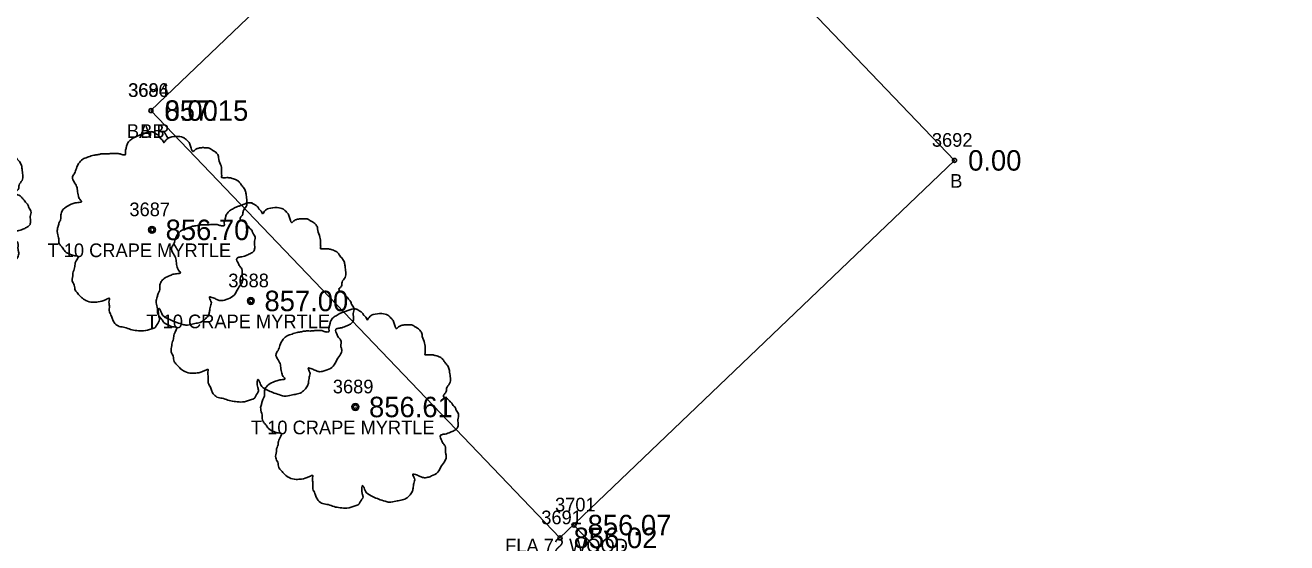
# Model space of a CAD drawing. Extents: x 1622501 to 1626664, y 1117816 to 1121579.
# Drawn here: x 1624818.4 to 1624910.8, y 1120179.9 to 1120217.8 of the extents above; entities that cross this region are included whole.
import ezdxf

# ---------------------------------------------------------------- set-up
doc = ezdxf.new("R2010")
doc.units = 0
for name, color, linetype in [('RD_EX_Bldg', 7, 'Continuous'), ('RD_EX_Bldg_txCode', 7, 'Continuous'), ('RD_EX_Fence_Other', 7, 'Continuous'), ('RD_EX_Fence_Other_txCode', 7, 'Continuous'), ('RD_EX_TX_Bldg_ELEV', 7, 'Continuous'), ('RD_EX_TX_Fence_Other_ELEV', 7, 'Continuous'), ('RD_EX_TX_VEG_ELEV', 7, 'Continuous'), ('RD_EX_VEG', 7, 'Continuous'), ('RD_EX_VEG_txCode', 7, 'Continuous'), ('RD_SMD_Locator', 7, 'Continuous')]:
    doc.layers.add(name, color=color, linetype=linetype)

msp = doc.modelspace()

# ---------------------------------------------------------------- linework, layer by layer
at = {"layer": 'RD_EX_Bldg'}
msp.add_lwpolyline([(1624827.624, 1120211.526), (1624857.59, 1120180.217), (1624886.487, 1120207.875), (1624856.521, 1120239.184), (1624827.624, 1120211.526)], dxfattribs=at)
at = {"layer": 'RD_EX_Fence_Other'}
msp.add_lwpolyline([(1624858.614, 1120181.158), (1624885.841, 1120152.998), (1624885.793, 1120151.157), (1624925.786, 1120193.73), (1624921.287, 1120199.2), (1624921.287, 1120199.2), (1624965.414, 1120242.441), (1624960.474, 1120248.561)], dxfattribs=at)
at = {"layer": 'RD_EX_VEG'}
for centre, radius in [((1624827.703, 1120202.787), 0.25), ((1624827.691, 1120202.768), 0.0001), ((1624834.945, 1120197.577), 0.25), ((1624834.933, 1120197.558), 0.0001), ((1624842.605, 1120189.807), 0.25), ((1624842.592, 1120189.788), 0.0001)]:
    msp.add_circle(centre, radius, dxfattribs=at)
for points in [[(1624815.641, 1120199.363), (1624815.566, 1120199.538), (1624815.516, 1120199.788), (1624815.591, 1120199.763), (1624815.766, 1120199.713), (1624816.041, 1120199.588), (1624816.266, 1120199.513), (1624816.591, 1120199.538), (1624816.865, 1120199.638), (1624817.315, 1120199.913), (1624817.59, 1120200.388), (1624817.865, 1120200.787), (1624817.94, 1120201.112), (1624817.89, 1120201.337), (1624817.865, 1120201.837), (1624817.665, 1120202.087), (1624817.615, 1120202.212), (1624817.515, 1120202.612), (1624817.59, 1120202.662), (1624817.865, 1120202.712), (1624818.24, 1120202.836), (1624818.515, 1120202.961), (1624818.74, 1120203.136), (1624818.815, 1120203.361), (1624818.79, 1120203.761), (1624818.84, 1120204.161), (1624818.765, 1120204.311), (1624818.665, 1120204.461), (1624818.59, 1120204.661), (1624818.44, 1120204.811), (1624818.34, 1120204.961), (1624818.24, 1120205.06), (1624818.115, 1120205.21), (1624817.94, 1120205.335), (1624817.79, 1120205.385), (1624817.74, 1120205.535), (1624817.89, 1120205.735), (1624817.94, 1120205.835), (1624817.965, 1120206.06), (1624818.19, 1120206.41), (1624818.24, 1120206.81), (1624818.19, 1120207.235), (1624818.14, 1120207.509), (1624817.99, 1120207.784), (1624817.79, 1120208.034), (1624817.665, 1120208.209), (1624817.49, 1120208.334), (1624817.165, 1120208.459), (1624816.915, 1120208.509), (1624816.566, 1120208.509), (1624816.366, 1120208.559), (1624816.391, 1120208.609), (1624816.391, 1120208.759), (1624816.391, 1120209.034), (1624816.316, 1120209.484), (1624816.166, 1120209.983), (1624816.166, 1120210.008), (1624816.066, 1120210.258), (1624815.841, 1120210.458), (1624815.666, 1120210.558), (1624815.466, 1120210.683), (1624815.216, 1120210.708), (1624814.916, 1120210.708), (1624814.641, 1120210.658), (1624814.441, 1120210.558), (1624814.267, 1120210.433), (1624814.192, 1120210.583), (1624814.092, 1120210.883), (1624814.042, 1120211.033), (1624813.892, 1120211.208), (1624813.667, 1120211.408), (1624813.217, 1120211.533), (1624812.592, 1120211.458), (1624812.292, 1120211.258), (1624812.142, 1120211.083), (1624812.093, 1120211.208), (1624811.893, 1120211.408), (1624811.793, 1120211.583), (1624811.618, 1120211.708), (1624811.468, 1120211.808), (1624811.368, 1120211.858)], [(1624827.835, 1120209.954), (1624827.535, 1120209.979), (1624827.211, 1120209.879), (1624826.961, 1120209.779), (1624826.736, 1120209.704), (1624826.511, 1120209.604), (1624826.211, 1120209.43), (1624825.986, 1120209.23), (1624825.861, 1120208.98), (1624825.811, 1120208.755), (1624825.761, 1120208.48), (1624825.761, 1120208.305), (1624825.636, 1120208.28), (1624825.486, 1120208.305), (1624825.236, 1120208.38), (1624824.987, 1120208.38), (1624824.737, 1120208.38), (1624824.387, 1120208.355), (1624824.037, 1120208.355), (1624823.762, 1120208.305), (1624823.437, 1120208.255), (1624823.062, 1120208.13), (1624822.713, 1120208.005), (1624822.413, 1120207.755), (1624822.163, 1120207.28), (1624822.038, 1120206.931), (1624821.888, 1120206.681), (1624822.038, 1120206.231), (1624822.213, 1120205.881), (1624822.238, 1120205.681), (1624822.313, 1120205.256), (1624822.413, 1120205.031), (1624822.538, 1120204.831), (1624822.463, 1120204.807), (1624822.088, 1120204.757), (1624821.788, 1120204.657), (1624821.363, 1120204.432), (1624821.138, 1120204.207), (1624821.038, 1120203.882), (1624821.013, 1120203.532), (1624820.913, 1120203.332), (1624820.838, 1120203.057), (1624820.813, 1120202.982), (1624820.763, 1120202.657), (1624820.863, 1120202.208), (1624820.888, 1120201.858), (1624821.013, 1120201.633), (1624821.163, 1120201.458), (1624821.338, 1120201.208), (1624821.738, 1120200.983), (1624822.063, 1120200.883), (1624822.263, 1120200.858), (1624822.088, 1120200.358), (1624822.038, 1120200.009), (1624821.913, 1120199.609), (1624821.913, 1120199.534), (1624821.863, 1120199.059), (1624822.013, 1120198.734), (1624822.088, 1120198.359), (1624822.263, 1120198.134), (1624822.538, 1120197.835), (1624822.862, 1120197.61), (1624823.362, 1120197.485), (1624823.762, 1120197.51), (1624824.337, 1120197.685), (1624824.587, 1120197.76), (1624824.562, 1120197.585), (1624824.587, 1120197.21), (1624824.587, 1120196.785), (1624824.737, 1120196.46), (1624824.837, 1120196.185), (1624824.987, 1120195.935), (1624825.311, 1120195.711), (1624825.711, 1120195.636), (1624826.136, 1120195.486), (1624826.586, 1120195.411), (1624827.086, 1120195.386), (1624827.685, 1120195.536), (1624827.96, 1120195.661), (1624828.06, 1120195.835), (1624828.26, 1120196.21), (1624828.21, 1120196.435), (1624828.235, 1120197.035), (1624828.335, 1120196.86), (1624828.51, 1120196.51), (1624829.01, 1120196.21), (1624829.41, 1120196.035), (1624829.884, 1120195.885), (1624830.184, 1120195.81), (1624830.659, 1120195.885), (1624831.034, 1120195.96), (1624831.409, 1120196.085), (1624831.709, 1120196.36), (1624831.884, 1120196.635), (1624831.934, 1120196.91), (1624832.008, 1120197.285), (1624832.058, 1120197.46)], [(1624832.058, 1120197.46), (1624831.984, 1120197.635), (1624831.934, 1120197.885), (1624832.008, 1120197.86), (1624832.183, 1120197.81), (1624832.458, 1120197.685), (1624832.683, 1120197.61), (1624833.008, 1120197.635), (1624833.283, 1120197.735), (1624833.733, 1120198.01), (1624834.008, 1120198.484), (1624834.282, 1120198.884), (1624834.357, 1120199.209), (1624834.307, 1120199.434), (1624834.282, 1120199.934), (1624834.083, 1120200.184), (1624834.033, 1120200.308), (1624833.933, 1120200.708), (1624834.008, 1120200.758), (1624834.282, 1120200.808), (1624834.657, 1120200.933), (1624834.932, 1120201.058), (1624835.157, 1120201.233), (1624835.232, 1120201.458), (1624835.207, 1120201.858), (1624835.257, 1120202.258), (1624835.182, 1120202.408), (1624835.082, 1120202.557), (1624835.007, 1120202.757), (1624834.857, 1120202.907), (1624834.757, 1120203.057), (1624834.657, 1120203.157), (1624834.532, 1120203.307), (1624834.357, 1120203.432), (1624834.208, 1120203.482), (1624834.158, 1120203.632), (1624834.307, 1120203.832), (1624834.357, 1120203.932), (1624834.382, 1120204.157), (1624834.607, 1120204.507), (1624834.657, 1120204.906), (1624834.607, 1120205.331), (1624834.557, 1120205.606), (1624834.407, 1120205.881), (1624834.208, 1120206.131), (1624834.083, 1120206.306), (1624833.908, 1120206.431), (1624833.583, 1120206.556), (1624833.333, 1120206.606), (1624832.983, 1120206.606), (1624832.783, 1120206.656), (1624832.808, 1120206.706), (1624832.808, 1120206.856), (1624832.808, 1120207.131), (1624832.733, 1120207.58), (1624832.583, 1120208.08), (1624832.583, 1120208.105), (1624832.483, 1120208.355), (1624832.258, 1120208.555), (1624832.083, 1120208.655), (1624831.884, 1120208.78), (1624831.634, 1120208.805), (1624831.334, 1120208.805), (1624831.059, 1120208.755), (1624830.859, 1120208.655), (1624830.684, 1120208.53), (1624830.609, 1120208.68), (1624830.509, 1120208.98), (1624830.459, 1120209.13), (1624830.309, 1120209.305), (1624830.084, 1120209.504), (1624829.634, 1120209.629), (1624829.01, 1120209.554), (1624828.71, 1120209.355), (1624828.56, 1120209.18), (1624828.51, 1120209.305), (1624828.31, 1120209.504), (1624828.21, 1120209.679), (1624828.035, 1120209.804), (1624827.885, 1120209.904), (1624827.785, 1120209.954)], [(1624835.077, 1120204.744), (1624834.777, 1120204.769), (1624834.453, 1120204.669), (1624834.203, 1120204.569), (1624833.978, 1120204.494), (1624833.753, 1120204.394), (1624833.453, 1120204.219), (1624833.228, 1120204.019), (1624833.103, 1120203.77), (1624833.053, 1120203.545), (1624833.003, 1120203.27), (1624833.003, 1120203.095), (1624832.878, 1120203.07), (1624832.728, 1120203.095), (1624832.478, 1120203.17), (1624832.229, 1120203.17), (1624831.979, 1120203.17), (1624831.629, 1120203.145), (1624831.279, 1120203.145), (1624831.004, 1120203.095), (1624830.679, 1120203.045), (1624830.304, 1120202.92), (1624829.955, 1120202.795), (1624829.655, 1120202.545), (1624829.405, 1120202.07), (1624829.28, 1120201.72), (1624829.13, 1120201.471), (1624829.28, 1120201.021), (1624829.455, 1120200.671), (1624829.48, 1120200.471), (1624829.555, 1120200.046), (1624829.655, 1120199.821), (1624829.78, 1120199.621), (1624829.705, 1120199.596), (1624829.33, 1120199.546), (1624829.03, 1120199.446), (1624828.605, 1120199.222), (1624828.38, 1120198.997), (1624828.28, 1120198.672), (1624828.255, 1120198.322), (1624828.155, 1120198.122), (1624828.08, 1120197.847), (1624828.055, 1120197.772), (1624828.005, 1120197.447), (1624828.105, 1120196.997), (1624828.13, 1120196.648), (1624828.255, 1120196.423), (1624828.405, 1120196.248), (1624828.58, 1120195.998), (1624828.98, 1120195.773), (1624829.305, 1120195.673), (1624829.505, 1120195.648), (1624829.33, 1120195.148), (1624829.28, 1120194.798), (1624829.155, 1120194.399), (1624829.155, 1120194.324), (1624829.105, 1120193.849), (1624829.255, 1120193.524), (1624829.33, 1120193.149), (1624829.505, 1120192.924), (1624829.78, 1120192.624), (1624830.104, 1120192.4), (1624830.604, 1120192.275), (1624831.004, 1120192.3), (1624831.579, 1120192.474), (1624831.829, 1120192.549), (1624831.804, 1120192.375), (1624831.829, 1120192), (1624831.829, 1120191.575), (1624831.979, 1120191.25), (1624832.079, 1120190.975), (1624832.229, 1120190.725), (1624832.553, 1120190.5), (1624832.953, 1120190.425), (1624833.378, 1120190.275), (1624833.828, 1120190.2), (1624834.328, 1120190.175), (1624834.927, 1120190.325), (1624835.202, 1120190.45), (1624835.302, 1120190.625), (1624835.502, 1120191), (1624835.452, 1120191.225), (1624835.477, 1120191.825), (1624835.577, 1120191.65), (1624835.752, 1120191.3), (1624836.252, 1120191), (1624836.652, 1120190.825), (1624837.126, 1120190.675), (1624837.426, 1120190.6), (1624837.901, 1120190.675), (1624838.276, 1120190.75), (1624838.651, 1120190.875), (1624838.951, 1120191.15), (1624839.126, 1120191.425), (1624839.176, 1120191.7), (1624839.25, 1120192.075), (1624839.3, 1120192.25)], [(1624839.3, 1120192.25), (1624839.226, 1120192.425), (1624839.176, 1120192.674), (1624839.25, 1120192.649), (1624839.425, 1120192.599), (1624839.7, 1120192.474), (1624839.925, 1120192.4), (1624840.25, 1120192.425), (1624840.525, 1120192.524), (1624840.975, 1120192.799), (1624841.25, 1120193.274), (1624841.524, 1120193.674), (1624841.599, 1120193.999), (1624841.549, 1120194.224), (1624841.524, 1120194.723), (1624841.325, 1120194.973), (1624841.275, 1120195.098), (1624841.175, 1120195.498), (1624841.25, 1120195.548), (1624841.524, 1120195.598), (1624841.899, 1120195.723), (1624842.174, 1120195.848), (1624842.399, 1120196.023), (1624842.474, 1120196.248), (1624842.449, 1120196.648), (1624842.499, 1120197.047), (1624842.424, 1120197.197), (1624842.324, 1120197.347), (1624842.249, 1120197.547), (1624842.099, 1120197.697), (1624841.999, 1120197.847), (1624841.899, 1120197.947), (1624841.774, 1120198.097), (1624841.599, 1120198.222), (1624841.45, 1120198.272), (1624841.4, 1120198.422), (1624841.549, 1120198.622), (1624841.599, 1120198.722), (1624841.624, 1120198.947), (1624841.849, 1120199.296), (1624841.899, 1120199.696), (1624841.849, 1120200.121), (1624841.799, 1120200.396), (1624841.649, 1120200.671), (1624841.45, 1120200.921), (1624841.325, 1120201.096), (1624841.15, 1120201.221), (1624840.825, 1120201.346), (1624840.575, 1120201.396), (1624840.225, 1120201.396), (1624840.025, 1120201.446), (1624840.05, 1120201.496), (1624840.05, 1120201.645), (1624840.05, 1120201.92), (1624839.975, 1120202.37), (1624839.825, 1120202.87), (1624839.825, 1120202.895), (1624839.725, 1120203.145), (1624839.5, 1120203.345), (1624839.325, 1120203.445), (1624839.126, 1120203.57), (1624838.876, 1120203.595), (1624838.576, 1120203.595), (1624838.301, 1120203.545), (1624838.101, 1120203.445), (1624837.926, 1120203.32), (1624837.851, 1120203.47), (1624837.751, 1120203.77), (1624837.701, 1120203.919), (1624837.551, 1120204.094), (1624837.326, 1120204.294), (1624836.876, 1120204.419), (1624836.252, 1120204.344), (1624835.952, 1120204.144), (1624835.802, 1120203.969), (1624835.752, 1120204.094), (1624835.552, 1120204.294), (1624835.452, 1120204.469), (1624835.277, 1120204.594), (1624835.127, 1120204.694), (1624835.027, 1120204.744)], [(1624842.737, 1120196.974), (1624842.437, 1120196.999), (1624842.112, 1120196.899), (1624841.862, 1120196.799), (1624841.637, 1120196.724), (1624841.412, 1120196.624), (1624841.112, 1120196.45), (1624840.888, 1120196.25), (1624840.763, 1120196), (1624840.713, 1120195.775), (1624840.663, 1120195.5), (1624840.663, 1120195.325), (1624840.538, 1120195.3), (1624840.388, 1120195.325), (1624840.138, 1120195.4), (1624839.888, 1120195.4), (1624839.638, 1120195.4), (1624839.288, 1120195.375), (1624838.938, 1120195.375), (1624838.664, 1120195.325), (1624838.339, 1120195.275), (1624837.964, 1120195.15), (1624837.614, 1120195.025), (1624837.314, 1120194.775), (1624837.064, 1120194.301), (1624836.939, 1120193.951), (1624836.789, 1120193.701), (1624836.939, 1120193.251), (1624837.114, 1120192.901), (1624837.139, 1120192.701), (1624837.214, 1120192.276), (1624837.314, 1120192.052), (1624837.439, 1120191.852), (1624837.364, 1120191.827), (1624836.989, 1120191.777), (1624836.689, 1120191.677), (1624836.265, 1120191.452), (1624836.04, 1120191.227), (1624835.94, 1120190.902), (1624835.915, 1120190.552), (1624835.815, 1120190.352), (1624835.74, 1120190.077), (1624835.715, 1120190.002), (1624835.665, 1120189.678), (1624835.765, 1120189.228), (1624835.79, 1120188.878), (1624835.915, 1120188.653), (1624836.065, 1120188.478), (1624836.24, 1120188.228), (1624836.639, 1120188.003), (1624836.964, 1120187.903), (1624837.164, 1120187.878), (1624836.989, 1120187.379), (1624836.939, 1120187.029), (1624836.814, 1120186.629), (1624836.814, 1120186.554), (1624836.764, 1120186.079), (1624836.914, 1120185.754), (1624836.989, 1120185.379), (1624837.164, 1120185.155), (1624837.439, 1120184.855), (1624837.764, 1120184.63), (1624838.264, 1120184.505), (1624838.664, 1120184.53), (1624839.238, 1120184.705), (1624839.488, 1120184.78), (1624839.463, 1120184.605), (1624839.488, 1120184.23), (1624839.488, 1120183.805), (1624839.638, 1120183.48), (1624839.738, 1120183.205), (1624839.888, 1120182.955), (1624840.213, 1120182.731), (1624840.613, 1120182.656), (1624841.037, 1120182.506), (1624841.487, 1120182.431), (1624841.987, 1120182.406), (1624842.587, 1120182.556), (1624842.862, 1120182.681), (1624842.962, 1120182.856), (1624843.162, 1120183.23), (1624843.112, 1120183.455), (1624843.137, 1120184.055), (1624843.236, 1120183.88), (1624843.411, 1120183.53), (1624843.911, 1120183.23), (1624844.311, 1120183.055), (1624844.786, 1120182.905), (1624845.086, 1120182.831), (1624845.56, 1120182.905), (1624845.935, 1120182.98), (1624846.31, 1120183.105), (1624846.61, 1120183.38), (1624846.785, 1120183.655), (1624846.835, 1120183.93), (1624846.91, 1120184.305), (1624846.96, 1120184.48)], [(1624846.96, 1120184.48), (1624846.885, 1120184.655), (1624846.835, 1120184.905), (1624846.91, 1120184.88), (1624847.085, 1120184.83), (1624847.36, 1120184.705), (1624847.585, 1120184.63), (1624847.909, 1120184.655), (1624848.184, 1120184.755), (1624848.634, 1120185.03), (1624848.909, 1120185.504), (1624849.184, 1120185.904), (1624849.259, 1120186.229), (1624849.209, 1120186.454), (1624849.184, 1120186.954), (1624848.984, 1120187.204), (1624848.934, 1120187.329), (1624848.834, 1120187.728), (1624848.909, 1120187.778), (1624849.184, 1120187.828), (1624849.559, 1120187.953), (1624849.834, 1120188.078), (1624850.059, 1120188.253), (1624850.133, 1120188.478), (1624850.109, 1120188.878), (1624850.158, 1120189.278), (1624850.084, 1120189.428), (1624849.984, 1120189.578), (1624849.909, 1120189.778), (1624849.759, 1120189.927), (1624849.659, 1120190.077), (1624849.559, 1120190.177), (1624849.434, 1120190.327), (1624849.259, 1120190.452), (1624849.109, 1120190.502), (1624849.059, 1120190.652), (1624849.209, 1120190.852), (1624849.259, 1120190.952), (1624849.284, 1120191.177), (1624849.509, 1120191.527), (1624849.559, 1120191.927), (1624849.509, 1120192.351), (1624849.459, 1120192.626), (1624849.309, 1120192.901), (1624849.109, 1120193.151), (1624848.984, 1120193.326), (1624848.809, 1120193.451), (1624848.484, 1120193.576), (1624848.234, 1120193.626), (1624847.884, 1120193.626), (1624847.685, 1120193.676), (1624847.71, 1120193.726), (1624847.71, 1120193.876), (1624847.71, 1120194.151), (1624847.635, 1120194.6), (1624847.485, 1120195.1), (1624847.485, 1120195.125), (1624847.385, 1120195.375), (1624847.16, 1120195.575), (1624846.985, 1120195.675), (1624846.785, 1120195.8), (1624846.535, 1120195.825), (1624846.235, 1120195.825), (1624845.96, 1120195.775), (1624845.76, 1120195.675), (1624845.585, 1120195.55), (1624845.51, 1120195.7), (1624845.411, 1120196), (1624845.361, 1120196.15), (1624845.211, 1120196.325), (1624844.986, 1120196.525), (1624844.536, 1120196.649), (1624843.911, 1120196.575), (1624843.611, 1120196.375), (1624843.461, 1120196.2), (1624843.411, 1120196.325), (1624843.211, 1120196.525), (1624843.112, 1120196.699), (1624842.937, 1120196.824), (1624842.787, 1120196.924), (1624842.687, 1120196.974)]]:
    msp.add_spline(points, degree=3, dxfattribs=at)
at = {"layer": 'RD_SMD_Locator'}
for centre in [(1624827.624, 1120211.526), (1624827.624, 1120211.526), (1624886.487, 1120207.875), (1624827.703, 1120202.787), (1624834.945, 1120197.577), (1624842.605, 1120189.807), (1624858.614, 1120181.158), (1624857.59, 1120180.217)]:
    msp.add_circle(centre, 0.15, dxfattribs=at)

# ---------------------------------------------------------------- texts
at = {"layer": 'RD_EX_Bldg_txCode'}
for s, p in [('3686', (1624825.947, 1120212.526)), ('3694', (1624825.97, 1120212.526)), ('BA R', (1624825.868, 1120209.526)), ('BB', (1624826.844, 1120209.526)), ('3692', (1624884.833, 1120208.875)), ('B', (1624886.18, 1120205.875)), ('3691', (1624856.22, 1120181.217))]:
    msp.add_text(s, height=1, dxfattribs=at).set_placement(p)
at = {"layer": 'RD_EX_Fence_Other_txCode'}
for s, p in [('3701', (1624857.229, 1120182.158)), ('FLA 72 WOOD', (1624853.575, 1120179.158))]:
    msp.add_text(s, height=1, dxfattribs=at).set_placement(p)
at = {"layer": 'RD_EX_TX_Bldg_ELEV'}
for s, p in [('0.00', (1624828.624, 1120210.776)), ('857.15', (1624828.624, 1120210.776)), ('0.00', (1624887.487, 1120207.125)), ('856.02', (1624858.59, 1120179.467))]:
    msp.add_text(s, height=1.5, dxfattribs=at).set_placement(p)
at = {"layer": 'RD_EX_TX_Fence_Other_ELEV'}
msp.add_text('856.07', height=1.5, dxfattribs=at).set_placement((1624859.614, 1120180.408))
at = {"layer": 'RD_EX_TX_VEG_ELEV'}
for s, p in [('856.70', (1624828.703, 1120202.037)), ('857.00', (1624835.945, 1120196.827)), ('856.61', (1624843.605, 1120189.057))]:
    msp.add_text(s, height=1.5, dxfattribs=at).set_placement(p)
at = {"layer": 'RD_EX_VEG_txCode'}
for s, p in [('3687', (1624826.05, 1120203.787)), ('T 10 CRAPE MYRTLE', (1624820.054, 1120200.787)), ('3688', (1624833.292, 1120198.577)), ('T 10 CRAPE MYRTLE', (1624827.296, 1120195.577)), ('3689', (1624840.951, 1120190.807)), ('T 10 CRAPE MYRTLE', (1624834.955, 1120187.807))]:
    msp.add_text(s, height=1, dxfattribs=at).set_placement(p)

doc.saveas('drawing.dxf')
